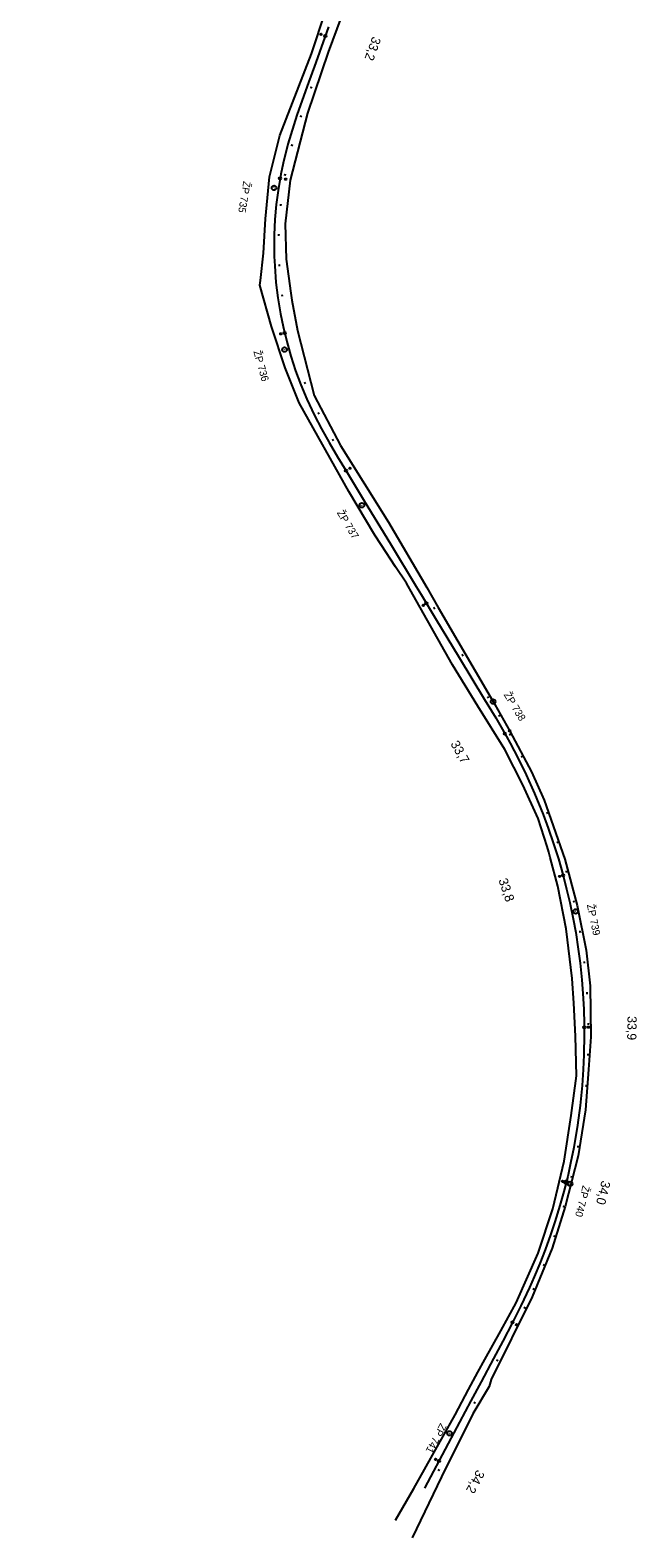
# Model space of a CAD drawing. Extents: x -792643 to -787072, y -1118436 to -1109677.
# Drawn here: x -787466 to -787072, y -1118436 to -1117454 of the extents above; entities that cross this region are included whole.
import ezdxf

# ---------------------------------------------------------------- set-up
doc = ezdxf.new("R2010")
doc.units = 0
for name, color, linetype in [('Vrstva 1', 7, 'Continuous'), ('Vrstva 53', 7, 'Continuous'), ('Vrstva 63', 7, 'Continuous'), ('Vrstva 7', 7, 'Continuous')]:
    doc.layers.add(name, color=color, linetype=linetype)

msp = doc.modelspace()

# ---------------------------------------------------------------- linework, layer by layer
at = {"layer": 'Vrstva 1'}
for points in [[(-787272.21, -1117452.2), (-787280.56, -1117475.36), (-787286.2, -1117490.98), (-787292.86, -1117509.71)], [(-787292.86, -1117509.71), (-787298.77, -1117528.62), (-787301.82, -1117540.93), (-787303.31, -1117548.18), (-787305.08, -1117558.82), (-787306.25, -1117568.01), (-787307.1, -1117577.72), (-787307.56, -1117587.67), (-787307.6, -1117599.17), (-787307.53, -1117601.83), (-787307.28, -1117607.9), (-787306.44, -1117618.66), (-787305.23, -1117628.66), (-787303.5, -1117639.15), (-787301.84, -1117647.31), (-787299.47, -1117657.06), (-787296.77, -1117666.62), (-787293.66, -1117676.11), (-787290.25, -1117685.27), (-787286.35, -1117694.59), (-787281.34, -1117705.24), (-787276.74, -1117714.02), (-787271.82, -1117722.76), (-787266.31, -1117732.11), (-787260.79, -1117741.26), (-787248.98, -1117760.78), (-787231.98, -1117788.82), (-787215.17, -1117816.52), (-787212.02, -1117821.73), (-787202.57, -1117837.35), (-787187.2, -1117862.72), (-787170.66, -1117890.04), (-787163.42, -1117902.05), (-787156.39, -1117914.22), (-787154.01, -1117918.54), (-787148.71, -1117928.62), (-787143.51, -1117939.27), (-787138.08, -1117951.3), (-787132.46, -1117965.09)], [(-787132.46, -1117965.09), (-787129.18, -1117973.86), (-787125.7, -1117983.98), (-787122.56, -1117993.91), (-787119.45, -1118004.79), (-787117.21, -1118013.49), (-787115.16, -1118022.25), (-787112.93, -1118032.96), (-787111.31, -1118041.88), (-787109.63, -1118052.65), (-787108.46, -1118061.67), (-787107.32, -1118072.54), (-787106.61, -1118081.54), (-787106.06, -1118091.61), (-787105.78, -1118101.45), (-787105.71, -1118108.23), (-787105.93, -1118121.35), (-787106.37, -1118131.07), (-787107.1, -1118141.41), (-787108.41, -1118154.51), (-787110.12, -1118167.31), (-787112.56, -1118181.74), (-787114.62, -1118192.05), (-787116.53, -1118200.54), (-787118.99, -1118210.4), (-787121.55, -1118219.6), (-787124.81, -1118230.22), (-787127.63, -1118238.71), (-787131.1, -1118248.3), (-787134.64, -1118257.32), (-787138.26, -1118265.93), (-787141.34, -1118272.83), (-787147.03, -1118284.81), (-787152.46, -1118295.63), (-787158.8, -1118307.84), (-787164.82, -1118319.21), (-787172.91, -1118334.4), (-787179.52, -1118346.77), (-787194.34, -1118374.51), (-787209.82, -1118403.42)]]:
    msp.add_lwpolyline(points, dxfattribs=at)
at = {"layer": 'Vrstva 53'}
for points in [[(-787458.26, -1117042.74), (-787398.26, -1117093.36), (-787375.17, -1117114.73), (-787356.91, -1117130.76), (-787352.43, -1117134.69), (-787327.03, -1117156.98), (-787300.85, -1117181.82), (-787277.47, -1117212.02), (-787259.63, -1117245.84), (-787255.58, -1117252.15), (-787244.19, -1117287.3), (-787240.18, -1117309.09), (-787238.86, -1117328.3), (-787241.48, -1117360.62), (-787242.61, -1117376.43), (-787248.32, -1117401.92), (-787250.51, -1117405.41), (-787252.11, -1117404.13), (-787255.1, -1117413.5), (-787252.33, -1117414.61), (-787252.97, -1117416.89), (-787254.84, -1117421.14), (-787272.47, -1117468.81)], [(-787283.43, -1117469.91), (-787265.1, -1117414.39), (-787264.26, -1117412.91), (-787261.83, -1117409.67), (-787260.78, -1117411.06), (-787257.76, -1117401.7), (-787258.37, -1117397.06), (-787254.36, -1117380.85), (-787250.96, -1117360.68), (-787250.41, -1117335.48), (-787252.03, -1117308.63), (-787255.71, -1117285.12), (-787259.39, -1117269.6), (-787266.99, -1117249.13), (-787276.75, -1117230.94), (-787292.44, -1117206.89), (-787307.2, -1117190.47), (-787322.75, -1117175.25), (-787356.33, -1117146.67), (-787360.49, -1117143.13), (-787390.97, -1117117.19), (-787466.48, -1117052.03)], [(-787272.47, -1117468.81), (-787286.03, -1117508.52), (-787297.19, -1117551.99), (-787300.57, -1117580.56), (-787299.73, -1117603.52), (-787296.84, -1117625.58), (-787296.23, -1117630.19), (-787292.35, -1117650.03), (-787281.5, -1117692.34), (-787264.39, -1117724.76), (-787233.24, -1117774.71), (-787208.31, -1117817.12), (-787200.76, -1117830.15), (-787163.99, -1117893.46), (-787154.27, -1117910.76), (-787140.05, -1117937.14), (-787131.85, -1117955.61), (-787118.45, -1117994.16), (-787110.44, -1118024.18), (-787104.5, -1118053.26), (-787101.82, -1118076.58), (-787101.49, -1118109.72), (-787102.99, -1118131.07), (-787104.86, -1118157.23), (-787109.78, -1118187.27), (-787118.12, -1118220.15), (-787126.72, -1118247.35), (-787139.65, -1118278.87), (-787166.34, -1118332.73), (-787167.59, -1118337.44), (-787178.21, -1118355.17), (-787198.68, -1118396.25), (-787217.86, -1118435.86)], [(-787228.62, -1118424.3), (-787216.75, -1118403.66), (-787209.71, -1118391.41), (-787204.45, -1118381.96), (-787192.93, -1118361.27), (-787189.82, -1118355.68), (-787181.11, -1118339.31), (-787175.05, -1118327.91), (-787170.53, -1118319.75), (-787160.15, -1118301.02), (-787150.06, -1118282.8), (-787135.72, -1118250.46), (-787126.22, -1118221.67), (-787118.93, -1118190.73), (-787114.26, -1118160.92), (-787110.83, -1118135.11), (-787111.37, -1118109.37), (-787112.63, -1118087.76), (-787113.57, -1118071.69), (-787117.44, -1118039.43), (-787122.95, -1118011.67), (-787127.87, -1117993.07), (-787128.78, -1117989.61), (-787129.99, -1117985.77), (-787135.71, -1117967.62), (-787145.72, -1117945.71), (-787157.56, -1117922.69), (-787175.04, -1117894.4), (-787191.61, -1117867.54), (-787217.39, -1117821.69), (-787221.52, -1117814.46), (-787228.62, -1117803.68), (-787238.02, -1117789.4), (-787242.15, -1117783.25), (-787259.05, -1117754.75), (-787291.42, -1117697.04), (-787300.47, -1117674.13), (-787309.36, -1117647.22), (-787316.9, -1117620.47), (-787316.54, -1117617.47), (-787314.62, -1117599.54), (-787313.18, -1117577.14), (-787310.72, -1117549.93), (-787303.89, -1117523.03), (-787283.43, -1117469.91)]]:
    msp.add_lwpolyline(points, dxfattribs=at)
at = {"layer": 'Vrstva 63'}
for p, q in [((-787307.7, -1117556.99), (-787307.74, -1117557.18)), ((-787300.9, -1117662.29), (-787300.84, -1117662.49)), ((-787250.47, -1117763.75), (-787250.57, -1117763.58)), ((-787165.17, -1117891.42), (-787165.07, -1117891.59)), ((-787111.32, -1118028.15), (-787111.36, -1118027.96)), ((-787114.95, -1118205.52), (-787114.9, -1118205.32)), ((-787193.42, -1118367.73), (-787193.51, -1118367.91))]:
    msp.add_line(p, q, dxfattribs=at)
for centre in [(-787307.72, -1117557.08), (-787300.87, -1117662.39), (-787250.52, -1117763.67), (-787165.12, -1117891.51), (-787111.34, -1118028.06), (-787114.93, -1118205.42), (-787193.46, -1118367.82)]:
    msp.add_circle(centre, 1.51, dxfattribs=at)
at = {"layer": 'Vrstva 7'}
for p, q in [((-787277.08, -1117457.07), (-787277.12, -1117457.17)), ((-787283.08, -1117491.97), (-787284.03, -1117491.64)), ((-787283.39, -1117491.33), (-787283.72, -1117492.28)), ((-787289.81, -1117510.71), (-787290.76, -1117510.41)), ((-787290.14, -1117510.09), (-787290.44, -1117511.04)), ((-787295.65, -1117529.52), (-787296.62, -1117529.28)), ((-787296.01, -1117528.92), (-787296.26, -1117529.89)), ((-787300.04, -1117548.75), (-787301.03, -1117548.59)), ((-787300.45, -1117548.18), (-787300.62, -1117549.16)), ((-787300.17, -1117551.34), (-787300.19, -1117551.44)), ((-787302.91, -1117568.41), (-787303.91, -1117568.33)), ((-787303.37, -1117567.87), (-787303.45, -1117568.87)), ((-787304.19, -1117587.91), (-787305.19, -1117587.86)), ((-787304.67, -1117587.38), (-787304.72, -1117588.38)), ((-787303.83, -1117607.5), (-787304.83, -1117607.54)), ((-787304.35, -1117607.02), (-787304.31, -1117608.02)), ((-787302.01, -1117627.09), (-787302.99, -1117627.25)), ((-787302.58, -1117626.68), (-787302.42, -1117627.66)), ((-787303.33, -1117652.04), (-787303.3, -1117652.14)), ((-787287.19, -1117684.03), (-787288.12, -1117684.42)), ((-787287.85, -1117683.76), (-787287.46, -1117684.69)), ((-787278.37, -1117703.78), (-787279.28, -1117704.21)), ((-787278.37, -1117703.78), (-787279.28, -1117704.21)), ((-787279.04, -1117703.54), (-787278.61, -1117704.45)), ((-787279.04, -1117703.54), (-787278.61, -1117704.45)), ((-787269.03, -1117721.08), (-787269.89, -1117721.59)), ((-787269.03, -1117721.08), (-787269.89, -1117721.59)), ((-787269.71, -1117720.91), (-787269.2, -1117721.77)), ((-787269.71, -1117720.91), (-787269.2, -1117721.77)), ((-787258.29, -1117739.52), (-787258.24, -1117739.61)), ((-787258.29, -1117739.52), (-787258.24, -1117739.61)), ((-787210.54, -1117828.77), (-787210.49, -1117828.85)), ((-787202.96, -1117830.45), (-787203.82, -1117830.97)), ((-787203.65, -1117830.28), (-787203.13, -1117831.14)), ((-787184.52, -1117861.03), (-787185.37, -1117861.54)), ((-787185.2, -1117860.86), (-787184.69, -1117861.71)), ((-787167.99, -1117888.4), (-787168.85, -1117888.92)), ((-787168.68, -1117888.23), (-787168.16, -1117889.09)), ((-787160.74, -1117900.43), (-787161.59, -1117900.94)), ((-787161.42, -1117900.26), (-787160.91, -1117901.12)), ((-787154.33, -1117910.49), (-787154.28, -1117910.58)), ((-787153.64, -1117912.7), (-787154.52, -1117913.18)), ((-787154.32, -1117912.5), (-787153.84, -1117913.38)), ((-787145.91, -1117927.19), (-787146.81, -1117927.62)), ((-787146.58, -1117926.96), (-787146.14, -1117927.85)), ((-787129.52, -1117963.94), (-787130.44, -1117964.32)), ((-787130.17, -1117963.67), (-787129.79, -1117964.59)), ((-787122.7, -1117982.99), (-787123.65, -1117983.32)), ((-787123.34, -1117982.68), (-787123.01, -1117983.63)), ((-787121.74, -1118005.27), (-787121.71, -1118005.37)), ((-787116.93, -1118002.06), (-787117.9, -1118002.34)), ((-787117.55, -1118001.72), (-787117.28, -1118002.68)), ((-787112.1, -1118021.53), (-787113.08, -1118021.76)), ((-787112.7, -1118021.16), (-787112.48, -1118022.13)), ((-787108.1, -1118041.3), (-787109.09, -1118041.46)), ((-787108.67, -1118040.88), (-787108.52, -1118041.87)), ((-787105.34, -1118061.32), (-787106.34, -1118061.42)), ((-787105.89, -1118060.87), (-787105.79, -1118061.87)), ((-787103.52, -1118081.32), (-787104.52, -1118081.38)), ((-787104.05, -1118080.85), (-787103.99, -1118081.85)), ((-787102.61, -1118101.42), (-787103.61, -1118101.43)), ((-787103.12, -1118100.92), (-787103.11, -1118101.92)), ((-787103.01, -1118103.37), (-787103.01, -1118103.47)), ((-787102.84, -1118121.47), (-787103.84, -1118121.42)), ((-787103.32, -1118120.95), (-787103.36, -1118121.95)), ((-787104.03, -1118141.71), (-787105.02, -1118141.61)), ((-787104.48, -1118141.16), (-787104.58, -1118142.16)), ((-787109.3, -1118181.42), (-787110.28, -1118181.25)), ((-787109.71, -1118180.85), (-787109.88, -1118181.83)), ((-787119.8, -1118203.76), (-787119.83, -1118203.86)), ((-787113.48, -1118201.16), (-787114.45, -1118200.92)), ((-787113.85, -1118200.56), (-787114.09, -1118201.53)), ((-787118.55, -1118220.46), (-787119.5, -1118220.16)), ((-787118.88, -1118219.83), (-787119.17, -1118220.79)), ((-787124.64, -1118239.73), (-787125.59, -1118239.41)), ((-787124.96, -1118239.09), (-787125.27, -1118240.04)), ((-787131.59, -1118258.58), (-787132.51, -1118258.19)), ((-787131.86, -1118257.92), (-787132.25, -1118258.84)), ((-787138.36, -1118274.1), (-787139.26, -1118273.67)), ((-787138.59, -1118273.44), (-787139.02, -1118274.34)), ((-787144.14, -1118286.28), (-787145.03, -1118285.83)), ((-787144.36, -1118285.61), (-787144.81, -1118286.51)), ((-787149.84, -1118297.62), (-787150.73, -1118297.16)), ((-787150.05, -1118296.95), (-787150.51, -1118297.84)), ((-787149.67, -1118297.01), (-787149.72, -1118297.1)), ((-787162.02, -1118320.69), (-787162.9, -1118320.22)), ((-787162.23, -1118320.02), (-787162.7, -1118320.9)), ((-787176.72, -1118348.23), (-787177.6, -1118347.76)), ((-787176.92, -1118347.56), (-787177.39, -1118348.44)), ((-787202.49, -1118384.66), (-787202.54, -1118384.75)), ((-787200.08, -1118391.95), (-787200.96, -1118391.47)), ((-787200.28, -1118391.27), (-787200.75, -1118392.15))]:
    msp.add_line(p, q, dxfattribs=at)
for centre, radius in [((-787277.1, -1117457.12), 0.5), ((-787274.35, -1117458.12), 0.75), ((-787303.74, -1117550.8), 0.75), ((-787300.18, -1117551.39), 0.5), ((-787303.32, -1117652.09), 0.5), ((-787300.82, -1117651.49), 0.75), ((-787300.82, -1117651.49), 0.75), ((-787260.86, -1117741.13), 0.75), ((-787260.86, -1117741.13), 0.75), ((-787260.86, -1117741.13), 0.75), ((-787260.86, -1117741.13), 0.75), ((-787258.27, -1117739.57), 0.5), ((-787258.27, -1117739.57), 0.5), ((-787210.52, -1117828.81), 0.5), ((-787208.48, -1117827.58), 0.75), ((-787208.48, -1117827.58), 0.75), ((-787154.31, -1117910.54), 0.5), ((-787157.46, -1117912.36), 0.75), ((-787157.46, -1117912.36), 0.75), ((-787157.46, -1117912.36), 0.75), ((-787121.73, -1118005.32), 0.5), ((-787119.48, -1118004.68), 0.75), ((-787119.48, -1118004.68), 0.75), ((-787119.48, -1118004.68), 0.75), ((-787105.76, -1118103.45), 0.75), ((-787105.76, -1118103.45), 0.75), ((-787105.76, -1118103.45), 0.75), ((-787103.01, -1118103.42), 0.5), ((-787119.82, -1118203.81), 0.5), ((-787117.49, -1118204.39), 1.25), ((-787117.49, -1118204.39), 1.25), ((-787117.49, -1118204.39), 0.752), ((-787117.49, -1118204.39), 0.752), ((-787152.46, -1118295.63), 0.75), ((-787149.7, -1118297.05), 0.5), ((-787202.51, -1118384.7), 0.5), ((-787200.4, -1118385.83), 0.75), ((-787200.4, -1118385.83), 0.75)]:
    msp.add_circle(centre, radius, dxfattribs=at)

# ---------------------------------------------------------------- texts
at = {"layer": 'Vrstva 63'}
for s, rotation, p in [('ŽP 735', 260.52982, (-787327.64, -1117552.45)), ('ŽP 736', 285.81633, (-787321.2, -1117663.59)), ('ŽP 737', 301.16575, (-787266.99, -1117768.56)), ('ŽP 738', 301.05973, (-787158.34, -1117886.97)), ('ŽP 739', 281.72685, (-787104.08, -1118023.83)), ('ŽP 740', 255.96102, (-787106.76, -1118206.19)), ('ŽP 741', 241.88133, (-787199.39, -1118360.84))]:
    msp.add_text(s, height=4.8, rotation=rotation, dxfattribs=at).set_placement(p)
at = {"layer": 'Vrstva 7'}
for s, rotation, p in [('33,2', 250.19543, (-787243.56, -1117458.18)), ('33,7', 299.39367, (-787193.04, -1117918.96)), ('33,8', 288.57672, (-787161.68, -1118007.62)), ('33,9', 269.05666, (-787077.58, -1118096.22)), ('34,0', 255.96102, (-787094.38, -1118202.98)), ('34,2', 241.83142, (-787175.56, -1118391.1))]:
    msp.add_text(s, height=6, rotation=rotation, dxfattribs=at).set_placement(p)

doc.saveas('drawing.dxf')
